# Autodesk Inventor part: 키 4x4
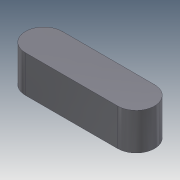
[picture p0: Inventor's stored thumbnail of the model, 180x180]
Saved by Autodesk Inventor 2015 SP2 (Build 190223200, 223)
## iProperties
Company: 한국ATC센터
Created: 2014-10
Part Number: 키 4x4
Document SubType Name: Modeling
Designer: KYOUNG IL JANG
Density: 7.85 g/cm^3
Mass: 1.65058 g
Surface Area: 2.35398 cm^2
Volume: 0.210265 cm^3
Material: 강철
Appearance: 강철 - 광택
Author: KYOUNG IL JANG
Revision Number: 1
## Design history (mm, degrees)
sketch "스케치1"
  geometry: L1 (-5, -2)-(5, -2); L2 (5, 2)-(-5, 2); A1 r 2 centre (5, 0) between (5, -2) and (5, 2); A2 r 2 centre (-5, 0) between (-5, 2) and (-5, -2); 2 further points
  constraints: 4 end point, 4 point on circle, 4 tangent, 2 centre point, 1 horizontal, 1 horizontal alignment, 1 midpoint, 1 parallel, 1 vertical alignment
  dimensions: "d0" = 4 distance between parallel lines of L1 L2; "d1" = 14 dimension on A1 A2
extrude "돌출1" new body sketch "스케치1" stored distance "d2" = 4; taper "d3" = 0 deg
node "솔리드1"
